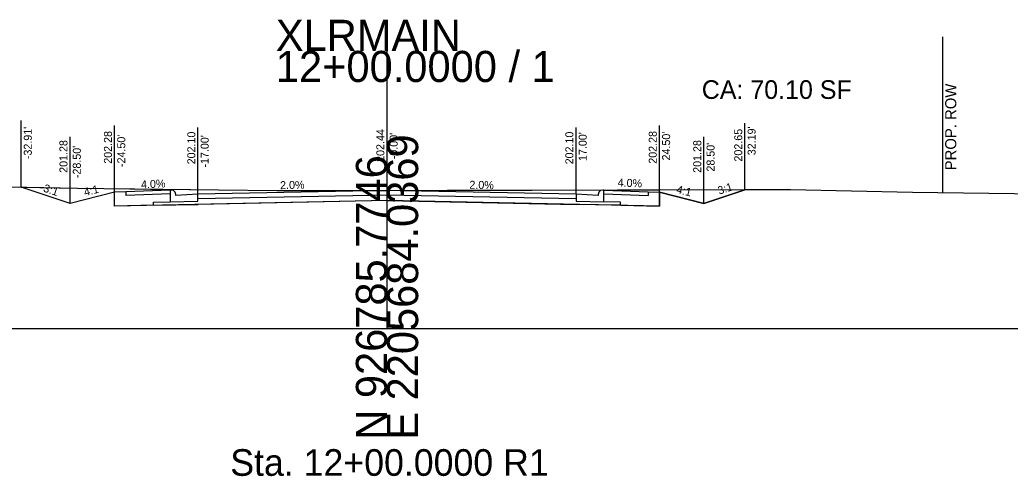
# Model space of a CAD drawing. Extents: x -26 to 303, y -13 to 1528.
# Drawn here: x 117 to 206, y 1486.7 to 1527.8 of the extents above; entities that cross this region are included whole.
import ezdxf

# ---------------------------------------------------------------- set-up
doc = ezdxf.new("R2010")
doc.units = 0
for name, color, linetype in [('CONST_DCH', 7, 'Continuous'), ('CONST_LV3', 7, 'Continuous'), ('Draft_XS_Text', 7, 'Continuous'), ('DTM_TEMP_DROP', 7, 'Continuous'), ('DTM_X_BOUNDARY', 7, 'Continuous'), ('SLOPE_STAKES_FILL', 7, 'Continuous'), ('XS_CELL', 7, 'Continuous'), ('XS_M_SHAPES_EARTHWORK', 7, 'Continuous'), ('XS_P_ASPHALT', 7, 'Continuous'), ('XS_P_CONCRETE', 7, 'Continuous'), ('XS_P_GROUND', 7, 'Continuous'), ('XS_P_ROW', 7, 'Continuous'), ('XS_P_SHOULDER', 7, 'Continuous'), ('XS_P_SUBGRADE_GRANULAR', 7, 'Continuous'), ('XS_P_SUBGRADE_GRANULAR_B', 7, 'Continuous'), ('XS_P_TX_CLEARZONE', 7, 'Continuous'), ('XS_P_TX_FS_BS', 7, 'Continuous'), ('XS_SHEET_EW_TX_AREA', 7, 'Continuous')]:
    doc.layers.add(name, color=color, linetype=linetype)

msp = doc.modelspace()

# ---------------------------------------------------------------- linework, layer by layer
at = {"layer": 'CONST_LV3'}
for points in [[(129, 1511.105), (129, 1511.397), (130.5, 1511.427)], [(171, 1511.106), (171, 1511.397), (169.5, 1511.427)]]:
    msp.add_lwpolyline(points, dxfattribs=at)
at = {"layer": 'DTM_X_BOUNDARY'}
msp.add_lwpolyline([(100.86, 1513.059), (122.175, 1512.65), (126.88, 1512.59), (127.216, 1512.586), (127.329, 1512.584), (128.716, 1512.567), (128.869, 1512.565), (128.878, 1512.565), (129.165, 1512.561), (129.217, 1512.56), (129.597, 1512.556), (140.09, 1512.422), (186.046, 1512.515), (186.277, 1512.512), (197.263, 1512.286), (222.421, 1511.967), (236.643, 1511.789), (241.161, 1511.506), (300, 1510.098)], dxfattribs=at)
at = {"layer": 'XS_CELL'}
for p, q in [((150, 1500), (150, 1525)), ((0, 1500), (150, 1500)), ((150, 1500), (300, 1500))]:
    msp.add_line(p, q, dxfattribs=at)
at = {"layer": 'XS_M_SHAPES_EARTHWORK'}
msp.add_lwpolyline([(150.018, 1511.526), (125.501, 1511.035), (125.5, 1512.277), (121.5, 1511.277), (117.091, 1512.747), (122.175, 1512.65), (124.528, 1512.62), (127.329, 1512.584), (134.843, 1512.489), (140.09, 1512.422), (150, 1512.442), (163.068, 1512.469), (186.046, 1512.515), (182.19, 1512.507), (178.5, 1511.277), (174.5, 1512.277), (174.499, 1511.036)], close=True, dxfattribs=at)
at = {"layer": 'XS_P_ASPHALT'}
for p, q in [((150, 1512.442), (133, 1512.102)), ((133, 1512.102), (133, 1512.102)), ((150.008, 1512.026), (133.008, 1511.686)), ((166.992, 1511.686), (149.992, 1512.026)), ((167, 1512.102), (150, 1512.442)), ((150, 1512.442), (150, 1512.442)), ((150, 1512.442), (150, 1512.442)), ((150, 1511.692), (150, 1511.692)), ((150, 1511.692), (150, 1511.692)), ((167, 1512.102), (167, 1512.102))]:
    msp.add_line(p, q, dxfattribs=at)
at = {"layer": 'XS_P_CONCRETE'}
for p, q in [((126.5, 1512.317), (126.5, 1511.987)), ((130.513, 1512.148), (126.5, 1511.987)), ((169.487, 1512.148), (173.5, 1511.987)), ((173.5, 1512.317), (173.5, 1511.987))]:
    msp.add_line(p, q, dxfattribs=at)
for points in [[(130.5, 1512.477), (126.5, 1512.317)], [(133, 1512.102), (131, 1511.977), (131, 1512.061), (131, 1512.061), (130.944, 1512.269), (130.944, 1512.269), (130.792, 1512.422), (130.792, 1512.422), (130.583, 1512.477), (130.583, 1512.477), (130.5, 1512.477), (130.5, 1512.477), (130.5, 1512.477), (130.5, 1511.427), (133, 1511.477), (133, 1511.477), (133, 1512.102), (133, 1512.102), (133, 1512.102)], [(167, 1512.102), (167, 1512.102), (167, 1512.102), (167, 1511.477), (167, 1511.477), (169.5, 1511.427), (169.5, 1512.477), (169.5, 1512.477), (169.417, 1512.477), (169.417, 1512.477), (169.417, 1512.477), (169.208, 1512.422), (169.208, 1512.422), (169.056, 1512.269), (169.056, 1512.269), (169, 1512.061), (169, 1512.061), (169, 1511.977), (167, 1512.102)], [(169.5, 1512.477), (173.5, 1512.317)]]:
    msp.add_lwpolyline(points, dxfattribs=at)
at = {"layer": 'XS_P_GROUND'}
for points in [[(121.5, 1511.277), (117.091, 1512.747)], [(178.5, 1511.277), (182.19, 1512.507)], [(125.5, 1512.277), (121.5, 1511.277)], [(174.5, 1512.277), (178.5, 1511.277)]]:
    msp.add_lwpolyline(points, dxfattribs=at)
at = {"layer": 'XS_P_ROW'}
msp.add_line((200, 1512.251), (200, 1526.251), dxfattribs=at)
at = {"layer": 'XS_P_SHOULDER'}
for points in [[(126.5, 1512.317), (125.5, 1512.277)], [(173.5, 1512.317), (174.5, 1512.277)]]:
    msp.add_lwpolyline(points, dxfattribs=at)
at = {"layer": 'XS_P_SUBGRADE_GRANULAR'}
for points in [[(129.018, 1511.106), (133.018, 1511.186)], [(150.018, 1511.526), (133.018, 1511.186)], [(150.018, 1511.526), (167.018, 1511.186)], [(171.018, 1511.106), (167.018, 1511.186)]]:
    msp.add_lwpolyline(points, dxfattribs=at)
at = {"layer": 'XS_P_SUBGRADE_GRANULAR_B'}
for points in [[(125.501, 1511.035), (125.5, 1512.277)], [(174.499, 1511.036), (174.5, 1512.277)], [(129.018, 1511.106), (125.501, 1511.035)], [(171.018, 1511.106), (174.499, 1511.036)]]:
    msp.add_lwpolyline(points, dxfattribs=at)
at = {"layer": 'XS_P_TX_CLEARZONE'}
for p, q in [((117.091, 1512.747), (117.091, 1518.747)), ((125.5, 1512.277), (125.5, 1518.277)), ((133, 1512.102), (133, 1518.102)), ((150, 1512.442), (150, 1518.442)), ((167, 1512.102), (167, 1518.102)), ((174.5, 1512.277), (174.5, 1518.277)), ((182.19, 1512.507), (182.19, 1518.507)), ((121.5, 1511.277), (121.5, 1517.277)), ((178.5, 1511.277), (178.5, 1517.277))]:
    msp.add_line(p, q, dxfattribs=at)

# ---------------------------------------------------------------- texts
at = {"layer": 'CONST_DCH'}
for p in [(132.996, 1512.096), (149.996, 1512.436), (166.996, 1512.096)]:
    msp.add_text('X', height=0.012, dxfattribs=at).set_placement(p)
at = {"layer": 'Draft_XS_Text'}
msp.add_text('Sta. 12+00.0000 R1', height=2.4, dxfattribs=at).set_placement((135.903, 1486.75))
at = {"layer": 'DTM_TEMP_DROP'}
for p in [(121.496, 1511.271), (178.496, 1511.271)]:
    msp.add_text('X', height=0.012, dxfattribs=at).set_placement(p)
at = {"layer": 'SLOPE_STAKES_FILL'}
for p in [(125.496, 1512.271), (174.496, 1512.271)]:
    msp.add_text('X', height=0.012, dxfattribs=at).set_placement(p)
at = {"layer": 'XS_CELL'}
for s, p in [('XLRMAIN', (140, 1525)), ('12+00.0000 / 1', (140, 1522.2))]:
    msp.add_text(s, height=2.8, dxfattribs=at).set_placement(p)
for s, p in [('E 2205684.0369', (152.8, 1490)), ('N 926785.7746', (150, 1490))]:
    msp.add_text(s, height=2.8, rotation=90, dxfattribs=at).set_placement(p)
at = {"layer": 'XS_P_CONCRETE'}
for p in [(117.087, 1512.741), (182.186, 1512.501)]:
    msp.add_text('X', height=0.012, dxfattribs=at).set_placement(p)
at = {"layer": 'XS_P_ROW'}
msp.add_text('PROP. ROW', height=1, rotation=90, dxfattribs=at).set_placement((201.2, 1514.251))
at = {"layer": 'XS_P_TX_CLEARZONE'}
for s, p in [("-32.91'", (118.051, 1515.257)), ('202.44', (149.76, 1515.009)), ('202.65', (181.95, 1515.039)), ("32.19'", (183.15, 1515.606)), ('201.28', (121.26, 1514.025)), ('202.28', (125.26, 1514.844)), ("-24.50'", (126.46, 1514.549)), ('202.10', (132.76, 1514.788)), ("-17.00'", (133.96, 1514.498)), ("-0.00'", (150.96, 1515.247)), ('202.10', (166.76, 1514.788)), ("17.00'", (167.96, 1515.088)), ('202.28', (174.26, 1514.844)), ("24.50'", (175.46, 1515.138)), ('201.28', (178.26, 1514.025)), ("-28.50'", (122.46, 1513.549)), ("-28.50'", (122.46, 1513.549)), ("28.50'", (179.46, 1514.138))]:
    msp.add_text(s, height=0.72, rotation=90, dxfattribs=at).set_placement(p)
at = {"layer": 'XS_P_TX_FS_BS'}
for s, rotation, p in [('4.0%', 2.33743, (127.891, 1512.621)), ('4.0%', 357.63463, (170.732, 1512.798)), ('3:1', 341.56505, (119.037, 1512.351)), ('4:1', 14.03624, (122.833, 1511.92)), ('2.0%', 1.14576, (140.392, 1512.55)), ('2.0%', 358.85424, (157.404, 1512.594)), ('4:1', 345.96376, (175.979, 1512.217)), ('3:1', 18.43495, (179.885, 1512.055))]:
    msp.add_text(s, height=0.72, rotation=rotation, dxfattribs=at).set_placement(p)
at = {"layer": 'XS_SHEET_EW_TX_AREA'}
msp.add_text('CA: 70.10 SF', height=1.68, dxfattribs=at).set_placement((178.309, 1520.678))

doc.saveas('drawing.dxf')
